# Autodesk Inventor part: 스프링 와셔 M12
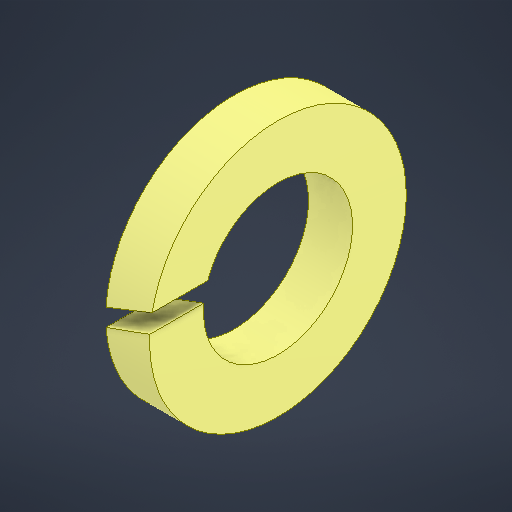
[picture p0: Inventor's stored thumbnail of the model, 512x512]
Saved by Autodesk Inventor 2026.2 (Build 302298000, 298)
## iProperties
Created: 2026-06
Part Number: 스프링 와셔 M12
Material: 강철, 연강
Description: 스프링 잠금 와셔
Document SubType Name: Modeling
Designer: sec7
Density: 7.85 g/cm^3
Appearance: 기본값
Author: jhkim
Sending System: Autodesk Inventor 2027
Preprocessor: ST-DEVELOPER v20.1
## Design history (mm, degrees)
feature "Solid1"
node "솔리드1"
